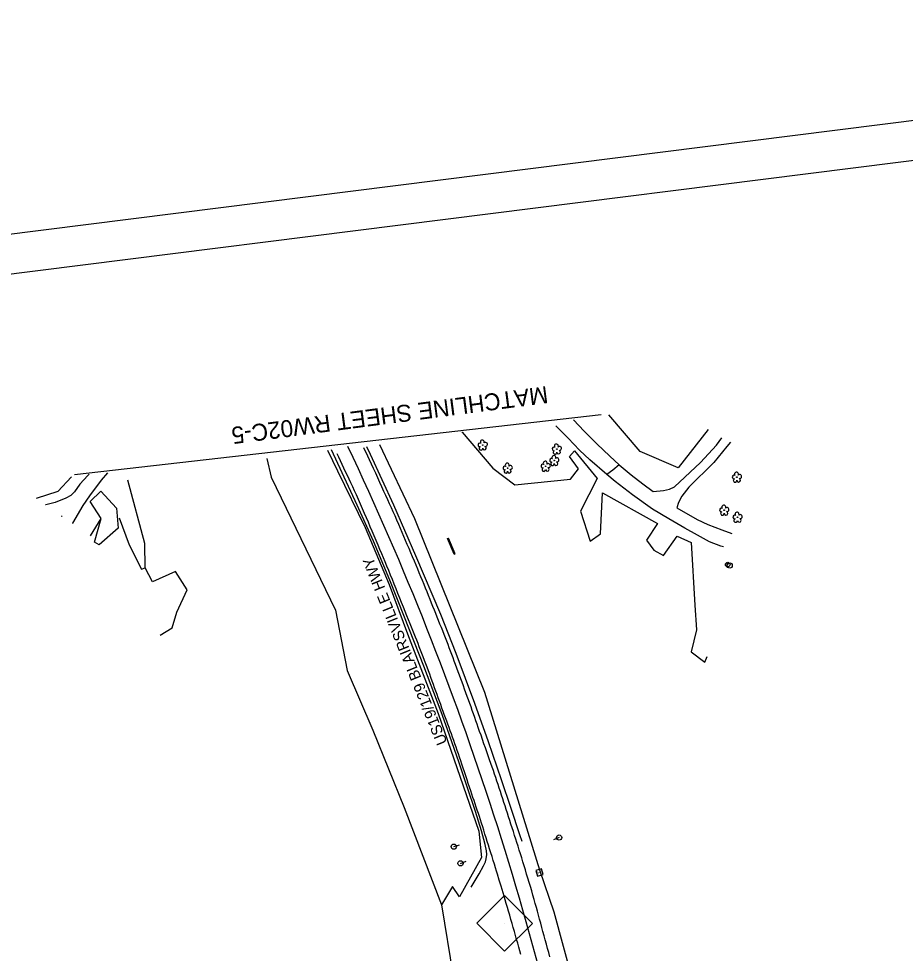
# Model space of a CAD drawing. Extents: x 476627 to 479509, y 495837 to 499842.
# Drawn here: x 477437 to 478274, y 498961 to 499842 of the extents above; entities that cross this region are included whole.
import ezdxf

# ---------------------------------------------------------------- set-up
doc = ezdxf.new("R2010")
doc.units = 0
for name, color, linetype in [('CTL Secondary Horizontal and Vertical CELL', 7, 'Continuous'), ('CTL Sheet Border CELL', 7, 'Continuous'), ('Exist Guardrail', 7, 'Continuous'), ('Exist Horizontal Alignment', 7, 'Continuous'), ('Exist Roads EOP', 7, 'Continuous'), ('Exist Roads EOP Text', 7, 'Continuous'), ('Exist Roads Soil', 7, 'Continuous'), ('Exist Structure Minor Head and End Wall', 7, 'Continuous'), ('Exist Utilities Other Located Object CELL', 7, 'Continuous'), ('Exist Utilities Other Pole CELL', 7, 'Continuous'), ('Exist Utilities Power Pole CELL', 7, 'Continuous'), ('Exist Utilities Telephone Pedestal CELL', 7, 'Continuous'), ('Exist Vegetation Hedge Row', 7, 'Continuous'), ('Exist Vegetation Tree CELL', 7, 'Continuous'), ('Exist Vegetation Woods Line', 7, 'Continuous'), ('Matchline', 7, 'Continuous'), ('Matchline Text', 7, 'Continuous'), ('Sheet Plot Border Outside CELL', 7, 'Continuous')]:
    doc.layers.add(name, color=color, linetype=linetype)

msp = doc.modelspace()

# ---------------------------------------------------------------- linework, layer by layer
at = {"layer": 'CTL Secondary Horizontal and Vertical CELL'}
msp.add_line((477895.6, 498988.85), (477895.6, 498988.85), dxfattribs=at)
msp.add_lwpolyline([(477869.53, 498988.94), (477895.74, 499015.15), (477921.99, 498988.9), (477895.78, 498962.69)], close=True, dxfattribs=at)
at = {"layer": 'CTL Sheet Border CELL'}
msp.add_lwpolyline([(476686.29, 499507.12), (477101.06, 496211.1), (479408.26, 496501.44), (478993.48, 499797.47)], close=True, dxfattribs=at)
at = {"layer": 'Exist Guardrail'}
for points in [[(477835.93, 499188.2), (477819.73, 499231.26), (477801.44, 499277.42), (477787.41, 499312.45), (477771.99, 499349.07), (477756.71, 499383.28), (477742.66, 499413.64), (477732.49, 499435.16)], [(477765.58, 499438.32), (477768.86, 499431.31), (477790.86, 499383.52), (477811.77, 499335.53), (477835.32, 499280.27), (477849.68, 499243.72), (477867.35, 499196.6)], [(477867.35, 499196.6), (477880.11, 499160.29), (477892.4, 499124.61), (477901.68, 499097.56), (477909.83, 499072.78), (477911.92, 499066.53)], [(477864.19, 499023.06), (477871.91, 499035.69), (477875.8, 499043.11), (477877.59, 499046.99), (477878.34, 499049.85), (477878.87, 499053.66), (477878.71, 499057.34), (477877.5, 499063.35), (477874.05, 499076.13), (477868.25, 499094.39), (477860.52, 499117.49), (477852.5, 499141.31), (477842.05, 499171.59), (477835.93, 499188.2)]]:
    msp.add_lwpolyline(points, dxfattribs=at)
at = {"layer": 'Exist Horizontal Alignment'}
msp.add_arc((475150.42, 498208.04), 2874.21, 10.42705, 25.34825, dxfattribs=at)
at = {"layer": 'Exist Roads EOP'}
for points in [[(478003.67, 499421.16), (477997.98, 499416.25), (477992.1, 499412.02), (477976.2, 499425.72), (477966.45, 499434.99), (477955.59, 499446.2), (477944.9, 499457.12), (477943.94, 499458.07)], [(477960.76, 499463.65), (477970.9, 499452.88), (477982.88, 499440.94), (477994.88, 499429.35), (478003.67, 499421.16)], [(477911.11, 498959.59), (477910.14, 498963.08), (477909.15, 498966.57), (477908.14, 498970.1), (477907.11, 498973.72), (477906.06, 498977.41), (477904.98, 498981.19), (477903.88, 498985), (477902.78, 498988.82), (477901.67, 498992.65), (477900.56, 498996.47), (477899.45, 499000.26), (477898.36, 499003.96), (477897.3, 499007.59), (477896.25, 499011.13), (477895.24, 499014.55), (477894.28, 499017.8), (477893.36, 499020.89), (477892.49, 499023.81), (477890.78, 499029.5), (477889.05, 499035.19), (477888.15, 499038.14), (477887.18, 499041.3), (477886.14, 499044.67), (477885.03, 499048.24), (477883.89, 499051.9), (477882.77, 499055.51), (477881.65, 499059.08), (477880.55, 499062.61), (477879.45, 499066.12), (477878.36, 499069.61), (477877.26, 499073.1), (477876.17, 499076.59), (477875.09, 499080.01), (477874.04, 499083.3), (477873.02, 499086.48), (477872.02, 499089.54), (477871.03, 499092.54), (477870.03, 499095.54), (477869.03, 499098.55), (477868.01, 499101.56), (477866.99, 499104.6), (477865.94, 499107.68), (477864.87, 499110.81), (477863.77, 499113.98), (477862.65, 499117.25), (477861.5, 499120.67), (477860.31, 499124.25), (477859.08, 499127.98), (477857.86, 499131.72), (477856.67, 499135.34), (477855.51, 499138.84), (477854.39, 499142.21), (477853.29, 499145.5), (477852.2, 499148.75), (477851.11, 499151.97), (477850.02, 499155.14), (477848.94, 499158.28), (477847.84, 499161.38), (477846.75, 499164.45), (477845.64, 499167.49), (477844.53, 499170.51), (477843.42, 499173.53), (477842.3, 499176.55), (477841.17, 499179.56), (477840.05, 499182.6), (477838.91, 499185.66), (477837.77, 499188.77), (477836.63, 499191.91), (477835.49, 499195.07), (477834.34, 499198.22), (477833.2, 499201.38), (477832.05, 499204.53), (477830.89, 499207.69), (477829.74, 499210.87), (477828.58, 499214.08), (477827.42, 499217.31), (477826.25, 499220.56), (477825.08, 499223.81), (477823.89, 499227.05), (477822.68, 499230.3), (477821.47, 499233.55), (477820.25, 499236.78), (477819.02, 499240.02), (477817.78, 499243.24), (477816.55, 499246.44), (477815.33, 499249.59), (477814.12, 499252.68), (477812.92, 499255.73), (477811.72, 499258.77), (477810.49, 499261.85), (477809.25, 499264.95), (477807.99, 499268.09), (477806.66, 499271.37), (477805.22, 499274.91), (477803.67, 499278.72), (477802.01, 499282.78), (477800.3, 499287), (477798.58, 499291.26), (477796.85, 499295.57), (477795.12, 499299.93), (477793.38, 499304.3), (477791.65, 499308.65), (477789.91, 499312.97), (477788.17, 499317.28), (477786.45, 499321.51), (477784.76, 499325.61), (477783.1, 499329.6), (477781.48, 499333.46), (477779.84, 499337.33), (477778.14, 499341.35), (477776.37, 499345.53), (477774.54, 499349.86), (477772.69, 499354.23), (477770.86, 499358.54), (477769.05, 499362.78), (477767.27, 499366.96), (477765.47, 499371.15), (477763.63, 499375.42), (477761.75, 499379.77), (477759.82, 499384.2), (477757.89, 499388.56), (477756.03, 499392.72), (477754.23, 499396.68), (477752.49, 499400.42), (477750.79, 499404.05), (477749.11, 499407.62), (477747.44, 499411.16), (477745.79, 499414.64), (477744.15, 499418.1), (477742.51, 499421.55), (477740.89, 499424.99), (477739.27, 499428.41), (477737.81, 499431.5)], [(477938.48, 498957.45), (477937.41, 498961.34), (477936.33, 498965.26), (477935.24, 498969.23), (477934.13, 498973.23), (477933.03, 498977.23), (477931.95, 498981.18), (477930.89, 498985.08), (477929.84, 498988.93), (477928.8, 498992.75), (477927.78, 498996.52), (477926.76, 499000.25), (477925.76, 499003.94), (477924.73, 499007.67), (477923.65, 499011.49), (477922.52, 499015.42), (477921.32, 499019.44), (477920.11, 499023.49), (477918.91, 499027.5), (477917.72, 499031.47), (477916.55, 499035.39), (477915.38, 499039.27), (477914.21, 499043.12), (477913.04, 499046.93), (477911.87, 499050.7), (477910.71, 499054.41), (477909.57, 499058.03), (477908.47, 499061.55), (477907.38, 499064.98), (477906.31, 499068.4), (477905.2, 499071.85), (477904.08, 499075.36), (477902.93, 499078.91), (477901.78, 499082.46), (477900.65, 499085.96), (477899.53, 499089.41), (477898.43, 499092.81), (477897.33, 499096.19), (477896.23, 499099.56), (477895.13, 499102.93), (477894.02, 499106.3), (477892.91, 499109.67), (477891.8, 499113.04), (477890.69, 499116.4), (477889.57, 499119.76), (477888.46, 499123.09), (477887.36, 499126.39), (477886.27, 499129.65), (477885.18, 499132.87), (477884.07, 499136.13), (477882.9, 499139.53), (477881.67, 499143.06), (477880.38, 499146.72), (477879.04, 499150.49), (477877.68, 499154.33), (477876.29, 499158.25), (477874.88, 499162.25), (477873.5, 499166.18), (477872.2, 499169.89), (477870.97, 499173.38), (477869.83, 499176.65), (477868.72, 499179.84), (477867.6, 499183.06), (477866.46, 499186.32), (477865.31, 499189.62), (477864.14, 499192.94), (477862.95, 499196.26), (477861.74, 499199.58), (477860.52, 499202.91), (477859.29, 499206.23), (477858.07, 499209.54), (477856.85, 499212.84), (477855.64, 499216.13), (477854.43, 499219.42), (477853.22, 499222.75), (477852, 499226.09), (477850.77, 499229.46), (477849.55, 499232.81), (477848.34, 499236.08), (477847.15, 499239.26), (477845.98, 499242.37), (477844.81, 499245.45), (477843.62, 499248.57), (477842.41, 499251.7), (477841.19, 499254.87), (477839.94, 499258.06), (477838.68, 499261.28), (477837.4, 499264.54), (477836.09, 499267.81), (477834.77, 499271.1), (477833.46, 499274.38), (477832.15, 499277.64), (477830.83, 499280.9), (477829.51, 499284.17), (477828.18, 499287.5), (477826.82, 499290.89), (477825.45, 499294.34), (477824.06, 499297.83), (477822.65, 499301.34), (477821.22, 499304.88), (477819.77, 499308.44), (477818.3, 499312.02), (477816.82, 499315.62), (477815.32, 499319.25), (477813.82, 499322.89), (477812.28, 499326.59), (477810.68, 499330.39), (477809.03, 499334.28), (477807.32, 499338.27), (477805.61, 499342.26), (477803.95, 499346.15), (477802.32, 499349.95), (477800.75, 499353.66), (477799.17, 499357.36), (477797.54, 499361.15), (477795.87, 499365.03), (477794.14, 499369), (477792.4, 499372.98), (477790.68, 499376.89), (477788.97, 499380.72), (477787.28, 499384.47), (477785.58, 499388.25), (477783.81, 499392.14), (477781.98, 499396.14), (477780.09, 499400.27), (477778.15, 499404.49), (477776.18, 499408.79), (477774.16, 499413.16), (477772.12, 499417.62), (477770.13, 499421.93), (477768.31, 499425.87), (477766.64, 499429.45), (477765.13, 499432.66), (477763.71, 499435.69), (477763.04, 499437.13)]]:
    msp.add_lwpolyline(points, dxfattribs=at)
at = {"layer": 'Exist Roads Soil'}
for points in [[(478035.99, 499396.12), (478045.68, 499396.9), (478051.36, 499398.07), (478056.12, 499400.35), (478080.38, 499423.27), (478095.62, 499439.57), (478100.62, 499446.56)], [(478108.84, 499442.58), (478105.46, 499438.54), (478093.14, 499423.21), (478069.53, 499400.14), (478063.08, 499391.67), (478059.84, 499385.65), (478058.22, 499380.65)], [(478003.67, 499421.16), (478015.22, 499411.83), (478026.12, 499403.36), (478035.99, 499396.12)], [(477488.38, 499365.72), (477488.63, 499366.19), (477498.3, 499382.93), (477504.54, 499392), (477515.49, 499406.73), (477521.57, 499413.61)], [(477503.99, 499412.25), (477502.62, 499410.99), (477495.2, 499402.86), (477490.01, 499395.63), (477486.63, 499392.33), (477481.79, 499389.75), (477471.88, 499385.71), (477462.94, 499383.42), (477462.76, 499383.38)], [(478102.11, 499343.71), (478099.84, 499344.49), (478088.99, 499348.63), (478077.78, 499354.93), (478065.77, 499361.47), (478050.63, 499370.17), (478035.13, 499379.34), (478016.46, 499392.99), (478000.07, 499405.5), (477992.1, 499412.02)], [(478058.22, 499380.65), (478077.35, 499369.66), (478087.52, 499365.02), (478100.56, 499359.76), (478109.98, 499356.56)], [(477477.65, 499373.12), (477478.28, 499372.78), (477478.37, 499372.62)]]:
    msp.add_lwpolyline(points, dxfattribs=at)
at = {"layer": 'Exist Structure Minor Head and End Wall'}
for p, q in [((477842, 499351.73), (477842.77, 499352.05)), ((477848.23, 499336.82), (477842, 499351.73)), ((477848.99, 499337.14), (477842.77, 499352.05)), ((477848.23, 499336.82), (477848.99, 499337.14))]:
    msp.add_line(p, q, dxfattribs=at)
at = {"layer": 'Exist Utilities Other Located Object CELL'}
for radius in [2.18, 0.24]:
    msp.add_circle((478106.18, 499327.06), radius, dxfattribs=at)
at = {"layer": 'Exist Utilities Other Pole CELL'}
msp.add_circle((478108.07, 499326.26), 2.46, dxfattribs=at)
at = {"layer": 'Exist Utilities Power Pole CELL'}
for p, q in [((477947.15, 499069.79), (477941.93, 499067.68)), ((477947.15, 499069.79), (477947.15, 499069.79)), ((477847.81, 499061.2), (477853.16, 499062.92)), ((477847.81, 499061.2), (477847.81, 499061.2)), ((477854.19, 499045.47), (477859.47, 499047.41)), ((477854.19, 499045.47), (477854.19, 499045.47))]:
    msp.add_line(p, q, dxfattribs=at)
for centre in [(477947.15, 499069.79), (477847.81, 499061.2), (477854.19, 499045.47)]:
    msp.add_circle(centre, 2.45, dxfattribs=at)
at = {"layer": 'Exist Utilities Telephone Pedestal CELL'}
msp.add_line((477928.73, 499036.66), (477928.73, 499036.66), dxfattribs=at)
msp.add_lwpolyline([(477932.21, 499034.83), (477930.64, 499040.2), (477925.27, 499038.64), (477926.84, 499033.27), (477932.21, 499034.83)], dxfattribs=at)
at = {"layer": 'Exist Vegetation Hedge Row'}
for points in [[(477728.72, 499434.9), (477738.08, 499415.64), (477764.09, 499362.16), (477786.75, 499308.23), (477804.08, 499261.98), (477832.94, 499186.67)], [(477505.08, 499354.22), (477515.37, 499370.64)], [(477532.25, 499371.1), (477541.74, 499345.58), (477553.21, 499322.95), (477556.8, 499323.98)], [(477832.94, 499186.67), (477871.32, 499075.85), (477873.97, 499050.92), (477853.29, 499013.77), (477846.72, 499023.73), (477836.35, 499006.26)]]:
    msp.add_lwpolyline(points, dxfattribs=at)
at = {"layer": 'Exist Vegetation Tree CELL'}
for p, q in [((477875.11, 499439.83), (477875.11, 499439.83)), ((477944.98, 499436.02), (477944.98, 499436.02)), ((477942.6, 499425.23), (477942.6, 499425.23)), ((477898.61, 499418.03), (477898.61, 499418.03)), ((477934.46, 499419.79), (477934.46, 499419.79)), ((478114.85, 499409.53), (478114.85, 499409.53)), ((478102.92, 499378.41), (478102.92, 499378.41)), ((478115.41, 499371.74), (478115.41, 499371.74))]:
    msp.add_line(p, q, dxfattribs=at)
for centre in [(477875.11, 499439.83), (477944.98, 499436.02), (477942.6, 499425.23), (477898.61, 499418.03), (477934.46, 499419.79), (478114.85, 499409.53), (478102.92, 499378.41), (478115.41, 499371.74)]:
    msp.add_circle(centre, 0.326, dxfattribs=at)
for centre, radius, start, end in [((477872.51, 499439.98), 1.73, 62.66361, 279.3457), ((477874.73, 499442.7), 1.86, 330.16508, 219.71335), ((477877.66, 499440.42), 1.9, 257.1011, 134.19993), ((477944.6, 499438.89), 1.86, 330.16508, 219.71335), ((477873.41, 499436.71), 1.69, 111.56708, 6.23104), ((477876.79, 499436.93), 1.7, 181.28216, 74.55999), ((477942.37, 499436.17), 1.73, 62.66361, 279.3457), ((477943.28, 499432.89), 1.69, 111.56708, 6.23104), ((477946.65, 499433.12), 1.7, 181.28216, 74.55999), ((477947.53, 499436.6), 1.9, 257.1011, 134.19993), ((477898.22, 499420.9), 1.86, 330.16508, 219.71335), ((477931.85, 499419.95), 1.73, 62.66361, 279.3457), ((477934.07, 499422.67), 1.86, 330.16508, 219.71335), ((477937.01, 499420.38), 1.9, 257.1011, 134.19993), ((477940, 499425.38), 1.73, 62.66361, 279.3457), ((477940.9, 499422.1), 1.69, 111.56708, 6.23104), ((477942.22, 499428.1), 1.86, 330.16508, 219.71335), ((477944.28, 499422.33), 1.7, 181.28216, 74.55999), ((477945.15, 499425.81), 1.9, 257.1011, 134.19993), ((477896, 499418.18), 1.73, 62.66361, 279.3457), ((477896.9, 499414.91), 1.69, 111.56708, 6.23104), ((477900.28, 499415.13), 1.7, 181.28216, 74.55999), ((477901.16, 499418.62), 1.9, 257.1011, 134.19993), ((477932.75, 499416.67), 1.69, 111.56708, 6.23104), ((477936.13, 499416.89), 1.7, 181.28216, 74.55999), ((478114.47, 499412.4), 1.86, 330.16508, 219.71335), ((478112.25, 499409.68), 1.73, 62.66361, 279.3457), ((478113.15, 499406.41), 1.69, 111.56708, 6.23104), ((478116.53, 499406.63), 1.7, 181.28216, 74.55999), ((478117.4, 499410.12), 1.9, 257.1011, 134.19993), ((478100.31, 499378.57), 1.73, 62.66361, 279.3457), ((478102.53, 499381.29), 1.86, 330.16508, 219.71335), ((478104.59, 499375.51), 1.7, 181.28216, 74.55999), ((478105.47, 499379), 1.9, 257.1011, 134.19993), ((478101.22, 499375.29), 1.69, 111.56708, 6.23104), ((478112.8, 499371.9), 1.73, 62.66361, 279.3457), ((478113.7, 499368.62), 1.69, 111.56708, 6.23104), ((478115.02, 499374.62), 1.86, 330.16508, 219.71335), ((478117.08, 499368.85), 1.7, 181.28216, 74.55999), ((478117.96, 499372.33), 1.9, 257.1011, 134.19993)]:
    msp.add_arc(centre, radius, start, end, dxfattribs=at)
at = {"layer": 'Exist Vegetation Woods Line'}
for points in [[(478087.88, 499454.52), (478059.42, 499418.24), (478023.64, 499433.61), (477994.22, 499468.31)], [(477855.5, 499452.06), (477855.62, 499451.8), (477884.54, 499418.14), (477905.53, 499402.35), (477958.07, 499407.7), (477965.36, 499417.48), (477956.91, 499428.92), (477961.7, 499434.22), (477983.04, 499408.3), (477967.34, 499377.46), (477976.43, 499349.14), (477986.28, 499356.24), (477987.94, 499394.78), (478039.94, 499365.86), (478029.48, 499350.15), (478036.65, 499340.68), (478045.78, 499335.72), (478058.38, 499354.01), (478071.77, 499347.93), (478075.23, 499288.75), (478076.78, 499265.48), (478071.84, 499244.87), (478084.68, 499235.03), (478086.69, 499240.45)], [(477877.26, 499206.51), (477811.22, 499370.1), (477778.05, 499440.02)], [(477671.38, 499427.06), (477675.72, 499409.52), (477736.13, 499284.21), (477747.19, 499227.37), (477771.36, 499171.02)], [(477487.24, 499409.88), (477474.25, 499396), (477453.9, 499389.49)], [(477570.96, 499260.57), (477582.1, 499267.57), (477586.6, 499282.13), (477596.43, 499303.23), (477585.37, 499320.75), (477563.74, 499310.86), (477556.8, 499323.98), (477556.43, 499346.86), (477540.51, 499406.79)], [(477504.94, 499386.55), (477514.96, 499396.2), (477529.54, 499380.22), (477531.24, 499361.49), (477513.28, 499345.63), (477508.92, 499348.35), (477515.37, 499370.64), (477504.94, 499386.55)], [(478182.3, 498910.77), (478166.83, 498916.31), (478107.63, 498907.49), (478070.29, 498915.49), (478054.1, 498865.86), (478062.04, 498834.83), (478043.51, 498754.74), (478021.79, 498715.6), (478012.98, 498719.06), (477998.42, 498777.13), (477977.8, 498870.01), (477942.42, 498999.34), (477929.03, 499039.05), (477877.26, 499206.51)], [(477771.36, 499171.02), (477801.04, 499098.02), (477836.35, 499006.26), (477847.24, 498939.21), (477882.23, 498850.13), (477903.45, 498797.63), (477909.74, 498774.45), (477889.45, 498735.82), (477899.46, 498701.89)]]:
    msp.add_lwpolyline(points, dxfattribs=at)
at = {"layer": 'Matchline'}
msp.add_line((477986.93, 499468.27), (477490.12, 499411.83), dxfattribs=at)
at = {"layer": 'Sheet Plot Border Outside CELL'}
msp.add_lwpolyline([(479509.37, 496141.41), (479043.71, 499841.75), (476626.65, 499537.58), (477092.31, 495837.24)], close=True, dxfattribs=at)

# ---------------------------------------------------------------- texts
at = {"layer": 'Exist Roads EOP Text'}
msp.add_text('US19/129 BLAIRSVILLE HWY', height=10.4, rotation=111.94585, dxfattribs=at).set_placement((477841.98, 499159.46))
at = {"layer": 'Exist Utilities Telephone Pedestal CELL'}
msp.add_text('T', height=3.42, rotation=106.24588, dxfattribs=at).set_placement((477930.69, 499036.05))
at = {"layer": 'Matchline Text'}
msp.add_text('MATCHLINE SHEET RW02C-5', height=16, rotation=187.44169, dxfattribs=at).set_placement((477935.59, 499495.43))

doc.saveas('drawing.dxf')
